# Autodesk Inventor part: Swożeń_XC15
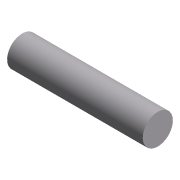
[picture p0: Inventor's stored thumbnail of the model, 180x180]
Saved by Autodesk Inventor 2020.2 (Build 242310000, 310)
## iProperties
Created: 2000-05
Part Number: Swożeń_XC15
Document SubType Name: Modeling
Designer: F.Stasiak
Stock Number: Swożeń_XC15
Density: 7.85 g/cm^3
Material: Stal
Appearance: Aluminium (matowe)
Mass: 221.954 g
Surface Area: 62.8319 cm^2
Volume: 28.2743 cm^3
Catalog Web Link: www.expertbooks.pl
Manager: www.cadconsulting.pl
Company: Fabian Stasiak CAD Consulting
Control State: 0
Master: False
Checked Out: False
Shininess: 0.0
Density: 0.0
Volumn: 0.0
Area: 0.0
PropertySet Name: Model Information
Author: F.Stasiak
Subject: Zbiór ćwiczeń. Autodesk Inventor 2020. Kurs Professional
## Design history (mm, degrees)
node "Base1"
node "Edytuj bezpośrednio1"
node "Bryła1"
node "Korpusy bryłowe"
node "Korpusy powierzchniowe"
feature "Przesuń1" dims "d2" = -5
other parameters: "d0" = 0, "d1" = 0
